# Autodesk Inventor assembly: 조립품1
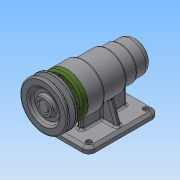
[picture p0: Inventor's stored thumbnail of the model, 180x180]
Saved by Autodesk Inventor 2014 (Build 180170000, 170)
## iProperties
Created: 2016-06
Part Number: 조립품1
Document SubType Name: Assembly
Designer: NET
Author: NET
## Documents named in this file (12)
- C:\Users\NET\Desktop\460607v1016\답안조립품.iam
- C:\Users\NET\Desktop\460607v1016\본체.ipt
- C:\Users\NET\Desktop\460607v1016\축.ipt
- C:\Users\NET\Desktop\460607v1016\키 5 x 5 x 16.ipt
- C:\Users\NET\Desktop\460607v1016\어댑터슬리브.ipt
- C:\Users\NET\Desktop\460607v1016\베어링 6004.ipt
- C:\Users\NET\Desktop\460607v1016\볼트 M4 x 12.ipt
- C:\Users\NET\Desktop\460607v1016\베어링 51202.ipt
- C:\Users\NET\Desktop\460607v1016\커버.ipt
- C:\Users\NET\Desktop\460607v1016\멈춤나사 M3x8.ipt
- C:\Users\NET\Desktop\460607v1016\V벨트풀리.ipt
- C:\Users\NET\Desktop\460607v1016\오일 실.ipt
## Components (6 placed, 2 different names)
1. ISO 4762 M4 x 12:1
2. V벨트풀리:1 — 각도:2
3. ISO 4762 M4 x 12:2
4. ISO 4762 M4 x 12:3
5. ISO 4762 M4 x 12:4
6. ISO 4762 M4 x 12:5
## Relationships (1: Angle 1)
- 각도:2 [Angle]: V벨트풀리:1
